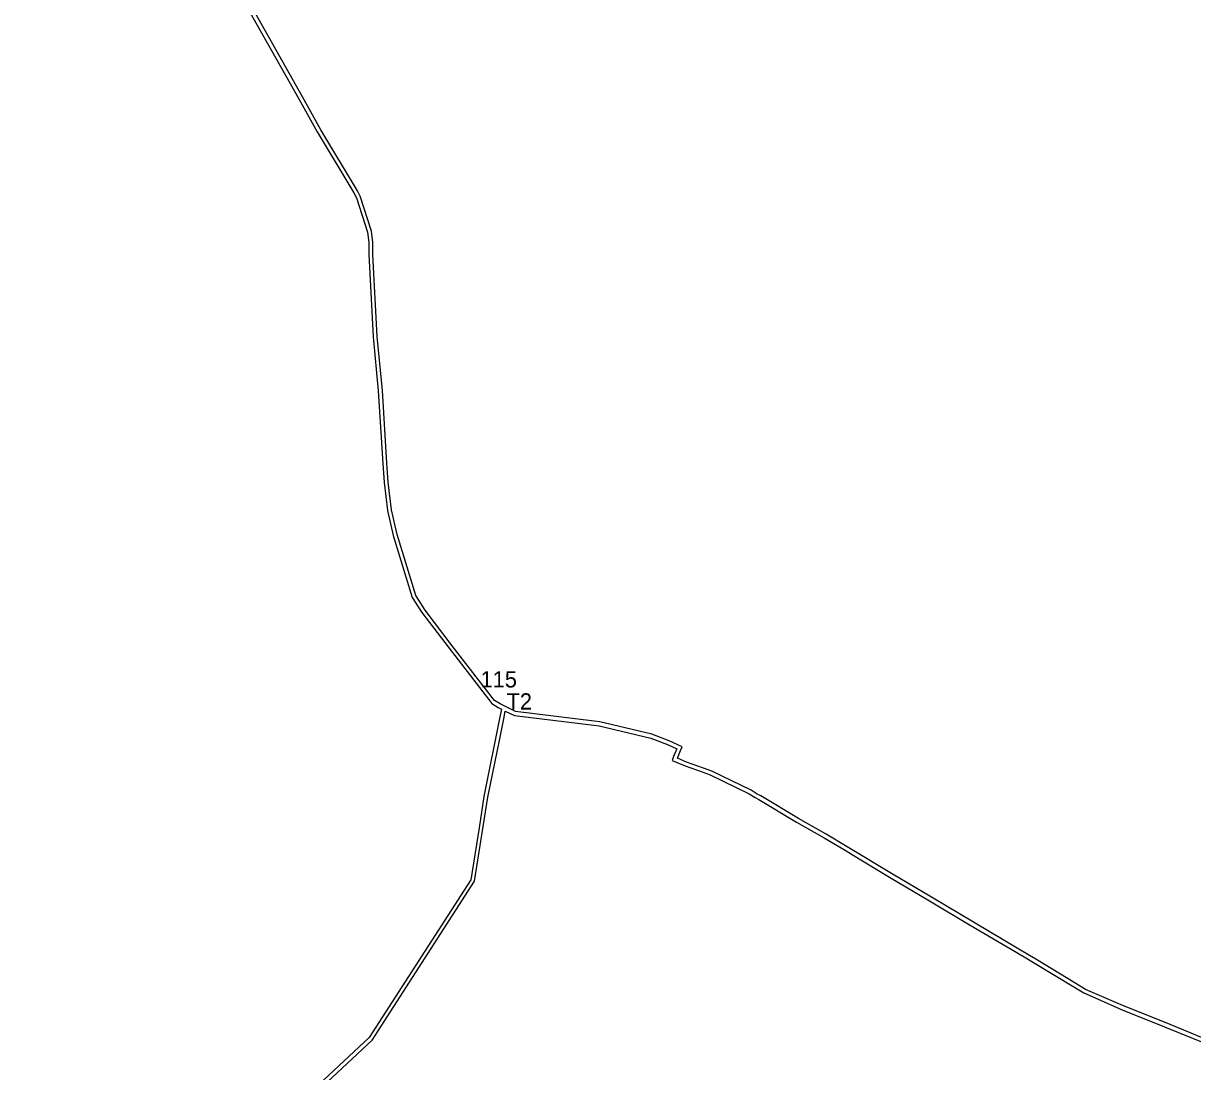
# Model space of a CAD drawing. Extents: x -477001 to -465642, y -1158278 to -1150672.
# Drawn here: x -471518 to -470657, y -1154869 to -1154097 of the extents above; entities that cross this region are included whole.
import ezdxf

# ---------------------------------------------------------------- set-up
doc = ezdxf.new("R2010")
doc.units = 0
for name, color, linetype in [('VPS_id', 7, 'Continuous'), ('VPS_n', 7, 'Continuous'), ('vyvlastneni_n', 7, 'Continuous')]:
    doc.layers.add(name, color=color, linetype=linetype)

msp = doc.modelspace()

# ---------------------------------------------------------------- linework, layer by layer
at = {"layer": 'VPS_n'}
for p, q in [((-471168.61, -1154601.15), (-471166.14, -1154602.35)), ((-471166.14, -1154602.35), (-471167.29, -1154608.09)), ((-471039.43, -1154637.31), (-471040.58, -1154640.07)), ((-471037, -1154631.51), (-471039.43, -1154637.31)), ((-471036.66, -1154638.47), (-471034.28, -1154632.76)), ((-471034.28, -1154632.76), (-471033.12, -1154629.99)), ((-471040.58, -1154640.07), (-471030.97, -1154644.14)), ((-471029.89, -1154641.34), (-471036.66, -1154638.47)), ((-471030.97, -1154644.14), (-471018.33, -1154648.58)), ((-471017.32, -1154645.76), (-471029.89, -1154641.34)), ((-471018.33, -1154648.58), (-471012.53, -1154650.71)), ((-471012.53, -1154650.71), (-470983.76, -1154664.69)), ((-471185.98, -1154729.1), (-471176.11, -1154667.16)), ((-470976.65, -1154668.84), (-470948.9, -1154685.47)), ((-470948.9, -1154685.47), (-470928.58, -1154697)), ((-470928.58, -1154697), (-470913.17, -1154706.25)), ((-470913.17, -1154706.25), (-470908.31, -1154709.18)), ((-470880.07, -1154722.71), (-470906.76, -1154706.61)), ((-470908.31, -1154709.18), (-470881.61, -1154725.28)), ((-470877.73, -1154724.1), (-470880.07, -1154722.71)), ((-470881.61, -1154725.28), (-470879.26, -1154726.68)), ((-470879.26, -1154726.68), (-470852.22, -1154742.7)), ((-470850.69, -1154740.12), (-470877.73, -1154724.1)), ((-470852.22, -1154742.7), (-470820.91, -1154761.26)), ((-470820.91, -1154761.26), (-470786.65, -1154781.57)), ((-470786.65, -1154781.57), (-470778.73, -1154786.26)), ((-470778.73, -1154786.26), (-470774.27, -1154788.96)), ((-470774.27, -1154788.96), (-470744.73, -1154806.88)), ((-470744.73, -1154806.88), (-470737.4, -1154811.32)), ((-470707.97, -1154820.84), (-470736.02, -1154808.65)), ((-470737.4, -1154811.32), (-470709.13, -1154823.61)), ((-470709.13, -1154823.61), (-470677.84, -1154836.15)), ((-471263.73, -1154844.09), (-471308.26, -1154885.7)), ((-470677.84, -1154836.15), (-470637.59, -1154852.71))]:
    msp.add_line(p, q, dxfattribs=at)
for points in [[(-471257.65, -1154328), (-471260.81, -1154267.52), (-471260.89, -1154258.59), (-471262, -1154250.4), (-471270.19, -1154224.63), (-471272.33, -1154220.76), (-471299.24, -1154175.76), (-471312.78, -1154151.43), (-471349.83, -1154085.83), (-471378.31, -1154036.45), (-471385.55, -1154027.49), (-471400.16, -1154014.56), (-471421.31, -1154003.31), (-471444.06, -1153992.04), (-471491.57, -1153971.33), (-471506.52, -1153963.51), (-471518.29, -1153956.42)], [(-471352.44, -1154087.32), (-471315.4, -1154152.9), (-471301.84, -1154177.26), (-471274.93, -1154222.26), (-471272.96, -1154225.82), (-471264.94, -1154251.06), (-471263.89, -1154258.81), (-471263.81, -1154267.61), (-471260.64, -1154328.22), (-471256.88, -1154368.05), (-471253.59, -1154421.36), (-471252.6, -1154435.38), (-471250.19, -1154456.17), (-471245.83, -1154474.48), (-471231.95, -1154520.04), (-471224.76, -1154531.26), (-471204.79, -1154557.5), (-471173.4, -1154598.23), (-471168.61, -1154601.15)], [(-471167.17, -1154598.51), (-471171.36, -1154595.96), (-471202.41, -1154555.68), (-471222.3, -1154529.54), (-471229.2, -1154518.77), (-471242.93, -1154473.69), (-471247.23, -1154455.65), (-471249.61, -1154435.1), (-471250.6, -1154421.16), (-471253.89, -1154367.82), (-471257.65, -1154328)], [(-471033.12, -1154629.99), (-471042.74, -1154625.58), (-471055.42, -1154620.85), (-471093.73, -1154611.7), (-471097.84, -1154611.19), (-471155.77, -1154604.06), (-471167.17, -1154598.51)], [(-471167.29, -1154608.09), (-471179.06, -1154666.63), (-471182.72, -1154689.61), (-471188.84, -1154728), (-471263.73, -1154844.09)], [(-471176.11, -1154667.16), (-471167.46, -1154624.12), (-471164.53, -1154609.57), (-471163.35, -1154603.71)], [(-471163.35, -1154603.71), (-471156.63, -1154606.98), (-471098.21, -1154614.17), (-471094.26, -1154614.66), (-471056.3, -1154623.73), (-471043.89, -1154628.35), (-471037, -1154631.51)], [(-470982.31, -1154662.06), (-471011.35, -1154647.95), (-471017.32, -1154645.76)], [(-470947.39, -1154682.88), (-470975.18, -1154666.23), (-470977.79, -1154664.84), (-470982.31, -1154662.06)], [(-470983.76, -1154664.69), (-470979.28, -1154667.45), (-470976.65, -1154668.84)], [(-470906.76, -1154706.61), (-470911.62, -1154703.68), (-470927.07, -1154694.41), (-470947.39, -1154682.88)], [(-471305.26, -1154887), (-471261.42, -1154846.03), (-471185.98, -1154729.1)], [(-470772.72, -1154786.39), (-470777.19, -1154783.69), (-470785.12, -1154778.99), (-470850.69, -1154740.12)], [(-470736.02, -1154808.65), (-470743.17, -1154804.31), (-470772.72, -1154786.39)], [(-470632.84, -1154851.42), (-470636.45, -1154849.93), (-470676.71, -1154833.37), (-470707.97, -1154820.84)]]:
    msp.add_lwpolyline(points, dxfattribs=at)
at = {"layer": 'vyvlastneni_n'}
for p, q in [((-471168.61, -1154601.15), (-471166.14, -1154602.35)), ((-471166.14, -1154602.35), (-471167.29, -1154608.09)), ((-471039.43, -1154637.31), (-471040.58, -1154640.07)), ((-471037, -1154631.51), (-471039.43, -1154637.31)), ((-471036.66, -1154638.47), (-471034.28, -1154632.76)), ((-471034.28, -1154632.76), (-471033.12, -1154629.99)), ((-471040.58, -1154640.07), (-471030.97, -1154644.14)), ((-471029.89, -1154641.34), (-471036.66, -1154638.47)), ((-471030.97, -1154644.14), (-471018.33, -1154648.58)), ((-471017.32, -1154645.76), (-471029.89, -1154641.34)), ((-471018.33, -1154648.58), (-471012.53, -1154650.71)), ((-471012.53, -1154650.71), (-470983.76, -1154664.69)), ((-471185.98, -1154729.1), (-471176.11, -1154667.16)), ((-470976.65, -1154668.84), (-470948.9, -1154685.47)), ((-470948.9, -1154685.47), (-470928.58, -1154697)), ((-470928.58, -1154697), (-470913.17, -1154706.25)), ((-470913.17, -1154706.25), (-470908.31, -1154709.18)), ((-470880.07, -1154722.71), (-470906.76, -1154706.61)), ((-470908.31, -1154709.18), (-470881.61, -1154725.28)), ((-470877.73, -1154724.1), (-470880.07, -1154722.71)), ((-470881.61, -1154725.28), (-470879.26, -1154726.68)), ((-470879.26, -1154726.68), (-470852.22, -1154742.7)), ((-470850.69, -1154740.12), (-470877.73, -1154724.1)), ((-470852.22, -1154742.7), (-470820.91, -1154761.26)), ((-470820.91, -1154761.26), (-470786.65, -1154781.57)), ((-470786.65, -1154781.57), (-470778.73, -1154786.26)), ((-470778.73, -1154786.26), (-470774.27, -1154788.96)), ((-470774.27, -1154788.96), (-470744.73, -1154806.88)), ((-470744.73, -1154806.88), (-470737.4, -1154811.32)), ((-470707.97, -1154820.84), (-470736.02, -1154808.65)), ((-470737.4, -1154811.32), (-470709.13, -1154823.61)), ((-470709.13, -1154823.61), (-470677.84, -1154836.15)), ((-471263.73, -1154844.09), (-471308.26, -1154885.7)), ((-470677.84, -1154836.15), (-470637.59, -1154852.71))]:
    msp.add_line(p, q, dxfattribs=at)
for points in [[(-471257.65, -1154328), (-471260.81, -1154267.52), (-471260.89, -1154258.59), (-471262, -1154250.4), (-471270.19, -1154224.63), (-471272.33, -1154220.76), (-471299.24, -1154175.76), (-471312.78, -1154151.43), (-471349.83, -1154085.83), (-471378.31, -1154036.45), (-471385.55, -1154027.49), (-471400.16, -1154014.56), (-471421.31, -1154003.31), (-471444.06, -1153992.04), (-471491.57, -1153971.33), (-471506.52, -1153963.51), (-471518.29, -1153956.42)], [(-471352.44, -1154087.32), (-471315.4, -1154152.9), (-471301.84, -1154177.26), (-471274.93, -1154222.26), (-471272.96, -1154225.82), (-471264.94, -1154251.06), (-471263.89, -1154258.81), (-471263.81, -1154267.61), (-471260.64, -1154328.22), (-471256.88, -1154368.05), (-471253.59, -1154421.36), (-471252.6, -1154435.38), (-471250.19, -1154456.17), (-471245.83, -1154474.48), (-471231.95, -1154520.04), (-471224.76, -1154531.26), (-471204.79, -1154557.5), (-471173.4, -1154598.23), (-471168.61, -1154601.15)], [(-471167.17, -1154598.51), (-471171.36, -1154595.96), (-471202.41, -1154555.68), (-471222.3, -1154529.54), (-471229.2, -1154518.77), (-471242.93, -1154473.69), (-471247.23, -1154455.65), (-471249.61, -1154435.1), (-471250.6, -1154421.16), (-471253.89, -1154367.82), (-471257.65, -1154328)], [(-471033.12, -1154629.99), (-471042.74, -1154625.58), (-471055.42, -1154620.85), (-471093.73, -1154611.7), (-471097.84, -1154611.19), (-471155.77, -1154604.06), (-471167.17, -1154598.51)], [(-471167.29, -1154608.09), (-471179.06, -1154666.63), (-471182.72, -1154689.61), (-471188.84, -1154728), (-471263.73, -1154844.09)], [(-471176.11, -1154667.16), (-471167.46, -1154624.12), (-471164.53, -1154609.57), (-471163.35, -1154603.71)], [(-471163.35, -1154603.71), (-471156.63, -1154606.98), (-471098.21, -1154614.17), (-471094.26, -1154614.66), (-471056.3, -1154623.73), (-471043.89, -1154628.35), (-471037, -1154631.51)], [(-470982.31, -1154662.06), (-471011.35, -1154647.95), (-471017.32, -1154645.76)], [(-470947.39, -1154682.88), (-470975.18, -1154666.23), (-470977.79, -1154664.84), (-470982.31, -1154662.06)], [(-470983.76, -1154664.69), (-470979.28, -1154667.45), (-470976.65, -1154668.84)], [(-470906.76, -1154706.61), (-470911.62, -1154703.68), (-470927.07, -1154694.41), (-470947.39, -1154682.88)], [(-471305.26, -1154887), (-471261.42, -1154846.03), (-471185.98, -1154729.1)], [(-470772.72, -1154786.39), (-470777.19, -1154783.69), (-470785.12, -1154778.99), (-470850.69, -1154740.12)], [(-470736.02, -1154808.65), (-470743.17, -1154804.31), (-470772.72, -1154786.39)], [(-470632.84, -1154851.42), (-470636.45, -1154849.93), (-470676.71, -1154833.37), (-470707.97, -1154820.84)]]:
    msp.add_lwpolyline(points, dxfattribs=at)

# ---------------------------------------------------------------- texts
at = {"layer": 'VPS_id'}
msp.add_text('115', height=12, dxfattribs=at).set_placement((-471181.55, -1154586.37))
at = {"layer": 'VPS_n'}
msp.add_text('T2', height=12, dxfattribs=at).set_placement((-471162.45, -1154602.66))

doc.saveas('drawing.dxf')
